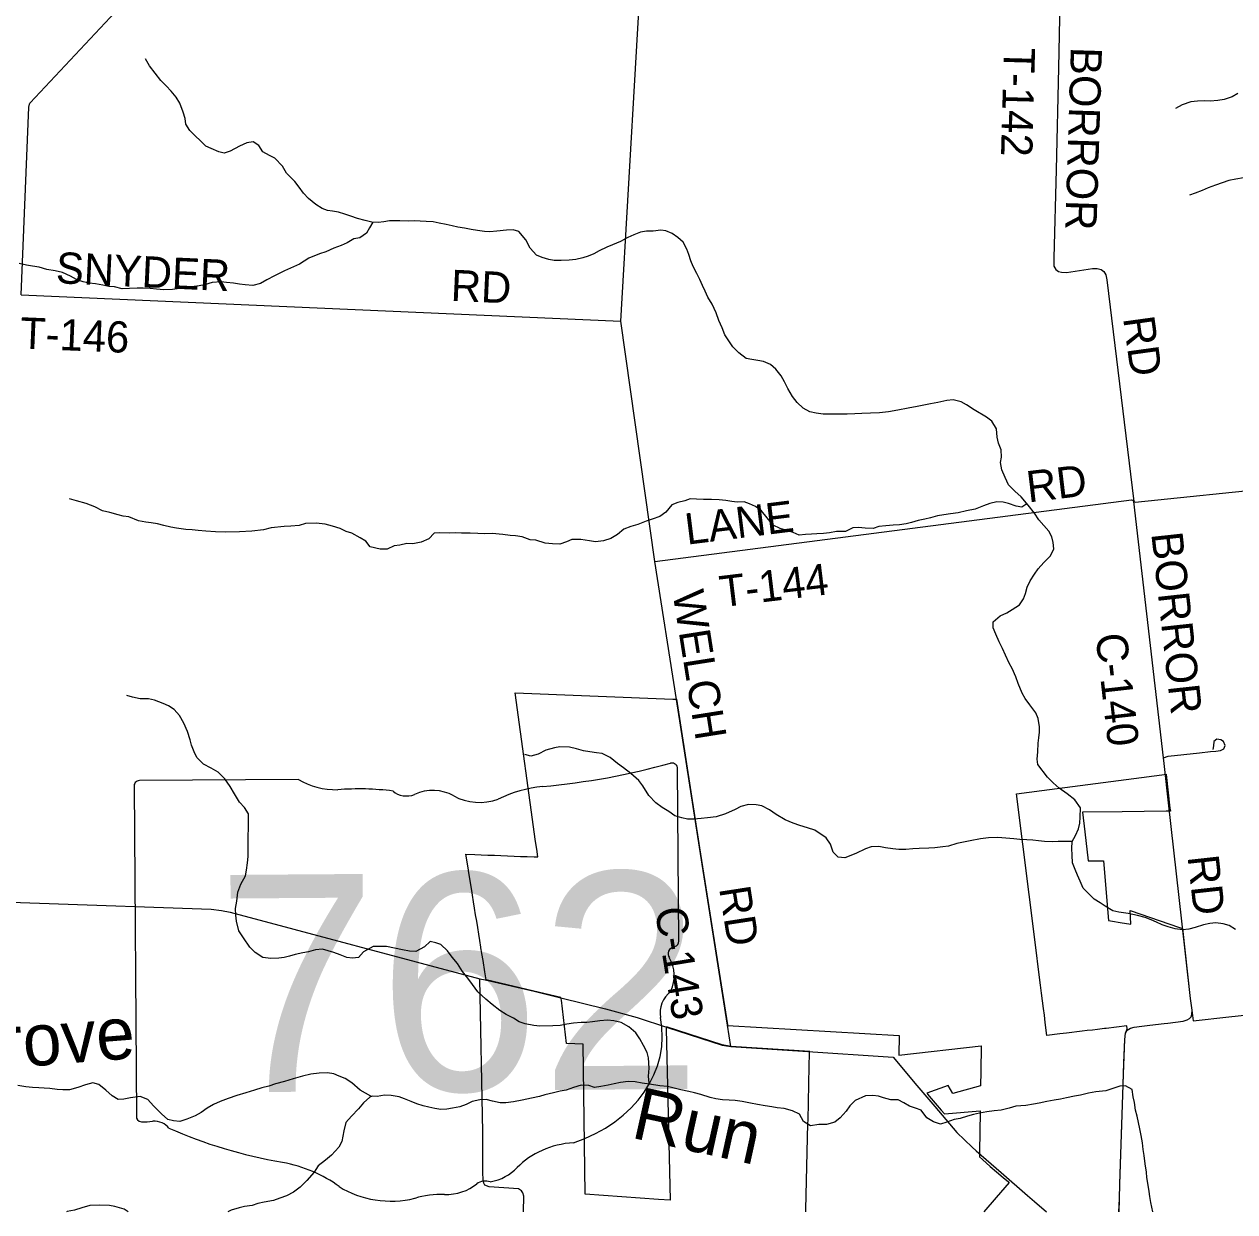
# Model space of a CAD drawing. Extents: x 114604 to 551442, y 316898 to 567001.
# Drawn here: x 179238 to 190868, y 317643 to 329055 of the extents above; entities that cross this region are included whole.
import ezdxf

# ---------------------------------------------------------------- set-up
doc = ezdxf.new("R2010")
doc.units = 0
for name, color, linetype in [('_CIVIL_CONSTRUCTION', 7, 'Continuous'), ('BD_X_Building', 7, 'Continuous'), ('GE_P_Alignment_1000_Cardinal_Points', 7, 'Continuous'), ('GE_P_Alignment_100_Stations', 7, 'Continuous'), ('GE_P_Alignment_500_Bearings', 7, 'Continuous'), ('GE_P_Alignment_500_Curve_Data', 7, 'Continuous'), ('PM_P_Cells', 7, 'Continuous'), ('PM_P_CL_Double_Solid', 7, 'Continuous'), ('PM_P_Crosswalk', 7, 'Continuous'), ('PM_P_Stop_Line', 7, 'Continuous')]:
    doc.layers.add(name, color=color, linetype=linetype)

msp = doc.modelspace()

# ---------------------------------------------------------------- linework, layer by layer
at = {"layer": '_CIVIL_CONSTRUCTION'}
for p, q in [((187814, 318858), (187986, 318656)), ((188944, 317742), (189058, 317643))]:
    msp.add_line(p, q, dxfattribs=at)
for points in [[(171255, 325243), (172108, 323234), (172499, 322309), (172537, 322236), (172596, 322172), (172685, 322099), (173053, 321844), (173629, 321425), (174426, 320802), (174474, 320772), (174528, 320749), (174593, 320740), (177732, 320667), (181033, 320552), (181132, 320540), (181218, 320522), (183615, 319883), (183667, 319871)], [(183667, 319871), (184136, 319762), (184394, 319699)], [(184394, 319699), (184822, 319594), (185128, 319509), (185417, 319415)], [(185417, 319415), (185736, 319312), (185943, 319245), (186028, 319231), (186719, 319186)], [(186719, 319186), (187585, 319130), (187814, 318858)], [(187986, 318656), (188198, 318405), (188345, 318265)], [(188345, 318265), (188383, 318228), (188624, 318020)], [(188624, 318020), (188876, 317801), (188944, 317742)]]:
    msp.add_lwpolyline(points, dxfattribs=at)
at = {"layer": 'GE_P_Alignment_1000_Cardinal_Points'}
msp.add_line((179210, 326456), (184971, 326203), dxfattribs=at)
for points in [[(179296, 328300), (180881, 329993), (181072, 330250)], [(189199, 329914), (189174, 328636), (189152, 327657), (189128, 326810), (189130, 326730), (189147, 326697), (189173, 326678), (189202, 326672), (189252, 326669), (189502, 326707), (189546, 326708), (189585, 326699), (189610, 326679), (189628, 326647), (189639, 326599), (189897, 324469)], [(179210, 326456), (179282, 328258), (179290, 328287), (179292, 328296), (179296, 328300)], [(185296, 323893), (189875, 324485), (189884, 324480), (189897, 324469)], [(190182, 322006), (190229, 322021), (190529, 322053), (190634, 322067), (190687, 322071), (190729, 322077), (190762, 322093), (190776, 322123), (190760, 322163), (190735, 322179), (190696, 322184), (190668, 322161), (190662, 322122), (190658, 322087)], [(184036, 317643), (184039, 317793), (184029, 317827), (184014, 317845), (183987, 317863), (183706, 317884), (183663, 317900), (183655, 317918), (183647, 317950), (183643, 318022), (183643, 318408), (183615, 319883)]]:
    msp.add_lwpolyline(points, dxfattribs=at)
at = {"layer": 'GE_P_Alignment_100_Stations'}
for points in [[(186748, 317643), (186748, 317665), (186767, 318491), (186768, 318525), (186780, 319042), (186783, 319164), (186784, 319184), (186027, 319233), (185942, 319248), (185407, 319422), (185406, 319400), (185443, 317756), (185333, 317763), (184628, 317812), (184609, 319255), (184448, 319262), (184399, 319677), (184394, 319701), (184135, 319765), (183675, 319872), (183672, 319893), (183670, 319911), (183664, 319948), (183646, 320058), (183635, 320125), (183629, 320165), (183626, 320181), (183625, 320187), (183615, 320249), (183605, 320311), (183595, 320374), (183585, 320436), (183575, 320498), (183565, 320560), (183555, 320623), (183545, 320685), (183538, 320731), (183535, 320747), (183525, 320809), (183511, 320900), (183503, 320950), (183482, 321079), (183566, 321076), (183629, 321074), (183692, 321071), (183755, 321069), (183818, 321066), (183881, 321064), (183944, 321061), (184007, 321059), (184070, 321057), (184136, 321054), (184172, 321053), (184162, 321128), (184151, 321203), (183956, 322629), (185468, 322569), (185503, 322569), (185727, 321142), (185994, 319441), (185995, 319433), (187645, 319339), (187641, 319148), (188432, 319239), (188428, 318991), (188425, 318855), (188158, 318780), (188114, 318858), (187910, 318782), (187932, 318756), (188048, 318621), (188078, 318585), (188421, 318613), (188421, 318600), (188416, 318224), (188415, 318170), (188443, 318145), (188517, 318080), (188579, 318026), (188644, 317972), (188693, 317930), (188700, 317924), (188576, 317780), (188458, 317643)], [(189755, 317643), (189759, 317772), (189764, 317911), (189792, 318768), (189802, 319075), (189811, 319299), (189818, 319361), (189831, 319391), (189833, 319403), (189830, 319429), (189633, 319405), (189617, 319404), (189549, 319396), (189500, 319390), (189450, 319384), (189400, 319378), (189351, 319372), (189301, 319367), (189251, 319361), (189186, 319353), (189063, 319339), (189047, 319463), (189039, 319532), (189030, 319597), (189021, 319671), (189012, 319745), (189002, 319820), (188990, 319919), (188953, 320209), (188770, 321661), (189015, 321692), (189898, 321807), (190168, 321842), (190208, 321847), (190212, 321815), (190245, 321523), (190249, 321492), (190209, 321492), (189785, 321487), (189404, 321483), (189426, 321293), (189459, 321015), (189607, 321016), (189653, 320441), (189692, 320435), (189767, 320424), (189868, 320408), (189864, 320540), (190336, 320376), (190365, 320365), (190440, 319694), (190455, 319582), (190468, 319479), (190809, 319516), (192176, 319665)]]:
    msp.add_lwpolyline(points, dxfattribs=at)
at = {"layer": 'GE_P_Alignment_500_Bearings'}
for p, q in [((185727, 321148), (185504, 322567)), ((190231, 321573), (190188, 321952)), ((190358, 320436), (190231, 321573)), ((185995, 319438), (185727, 321148)), ((186028, 319231), (185995, 319438))]:
    msp.add_line(p, q, dxfattribs=at)
for points in [[(185504, 322567), (185296, 323893), (184971, 326203), (185191, 330009)], [(189897, 324469), (189911, 324463), (192647, 324743)], [(190188, 321952), (190182, 322006), (189897, 324469)], [(190448, 319517), (190454, 319538), (190457, 319580), (190442, 319694), (190358, 320436)], [(190189, 319453), (190226, 319457), (190371, 319475), (190409, 319489), (190433, 319502), (190448, 319517)], [(189765, 317908), (189793, 318766), (189800, 318967), (189812, 319299), (189819, 319359), (189833, 319388), (189867, 319409)], [(189867, 319409), (189900, 319417), (189975, 319428)], [(189975, 319428), (190051, 319438), (190189, 319453)], [(189757, 317643), (189760, 317769), (189765, 317908)]]:
    msp.add_lwpolyline(points, dxfattribs=at)
at = {"layer": 'GE_P_Alignment_500_Curve_Data'}
for p, q in [((181874, 321798), (180345, 321787)), ((185526, 320245), (185514, 321903)), ((180294, 321732), (180317, 318562)), ((185525, 320245), (185526, 320245))]:
    msp.add_line(p, q, dxfattribs=at)
for centre, major_axis, ratio, start_param, end_param in [((183623, 326133), (5537, 40), 0.800001, 4.814395, 5.042369), ((185456, 321909), (58.1, 0.4), 0.8, 6.141152, 7.989035), ((182235, 322169), (587, 4), 0.8, 4.042523, 4.731795), ((180354, 321739), (60.5, 0.4), 0.8, 1.712693, 3.28349), ((182445, 320022), (2106, 15), 0.8, 1.404758, 1.657858), ((182911, 321774), (169, 1), 0.8, 3.836095, 5.185415), ((183162, 321410), (352, 3), 0.8, 0.950623, 2.079405), ((184368, 320848), (1114, 8), 0.8, 1.699011, 2.107814), ((183612, 321915), (423, 3), 0.8, 4.081561, 5.145723), ((185513, 320123), (89.9, 0.6), 0.8, 1.883978, 3.671073), ((185464, 320238), (62.2, 0.4), 0.8, 5.05454, 6.418171), ((184942, 319909), (540, 4), 0.8, 5.934695, 6.695948), ((185739, 319552), (393, 3), 0.8, 2.387724, 3.262537), ((183983, 319328), (1385, 10), 0.8, 5.101753, 6.440018), ((180377, 318556), (61, 0.4), 0.8, 3.00124, 4.508301), ((180384, 318880), (466, 3), 0.8, 4.665946, 4.897461), ((180483, 318380), (168, 1), 0.8, 0.519207, 1.627899), ((182582, 321244), (3998, 29), 0.8, 4.195996, 4.48896), ((184578, 317703), (758, 5), 0.8, 1.647645, 2.488434), ((181420, 317146), (1251, 9), 0.8, 0.823519, 1.323588), ((183613, 318279), (447, 3), 0.8, 4.937069, 5.64225), ((182764, 318381), (794, 6), 0.8, 4.026481, 4.996735), ((183282, 318147), (423, 3), 0.8, 4.691044, 5.507374), ((183667, 317843), (119, 1), 0.8, 1.147584, 2.315152), ((183230, 317288), (652, 5), 0.8, 1.495662, 1.94098)]:
    msp.add_ellipse(centre, major_axis=major_axis, ratio=ratio, start_param=start_param, end_param=end_param, dxfattribs=at)
at = {"layer": 'PM_P_Cells'}
for points in [[(185603, 326893), (185568, 326959), (185518, 327006), (185463, 327043), (185403, 327070), (185353, 327077), (185279, 327066), (185215, 327065), (185159, 327056), (185095, 327031), (185038, 327004), (184965, 326967), (184891, 326935), (184835, 326914), (184762, 326877), (184709, 326848), (184657, 326827), (184605, 326810), (184538, 326795), (184474, 326788), (184396, 326785), (184328, 326783), (184278, 326795), (184215, 326814), (184161, 326835), (184098, 326902), (184057, 326983), (183989, 327063), (183935, 327080), (183871, 327077), (183779, 327065), (183712, 327060), (183660, 327063), (183593, 327074), (183533, 327083), (183467, 327094), (183405, 327105), (183349, 327116), (183293, 327131), (183226, 327144), (183166, 327155), (183100, 327160), (183042, 327163), (182990, 327164), (182926, 327163), (182848, 327164), (182748, 327164), (182692, 327157), (182639, 327148), (182579, 327153), (182512, 327168), (182440, 327189), (182376, 327210), (182319, 327231), (182257, 327248), (182201, 327257), (182151, 327264), (182099, 327285), (182040, 327323), (181969, 327380), (181922, 327433), (181881, 327488), (181837, 327542), (181759, 327625), (181718, 327690), (181647, 327767), (181593, 327792), (181530, 327829), (181491, 327891), (181438, 327926), (181377, 327915), (181307, 327882), (181218, 327836), (181158, 327817), (181108, 327828), (181034, 327861), (180983, 327884), (180933, 327934), (180880, 327983), (180829, 328032), (180792, 328094), (180783, 328150), (180764, 328210), (180733, 328295), (180698, 328353), (180649, 328412), (180602, 328464), (180551, 328513), (180441, 328655), (180404, 328723)], [(190898, 328390), (190843, 328357), (190765, 328330), (190704, 328323), (190632, 328317), (190576, 328318), (190510, 328315), (190446, 328310), (190362, 328279), (190297, 328246)], [(191590, 327427), (191540, 327436), (191487, 327467), (191422, 327530), (191348, 327549), (191292, 327572), (191227, 327585), (191133, 327588), (191069, 327585), (191008, 327581), (190952, 327579), (190878, 327567), (190812, 327552), (190745, 327531), (190683, 327508), (190611, 327483), (190554, 327458), (190488, 327432), (190433, 327411)], [(182586, 327153), (182556, 327097), (182526, 327046), (182463, 327003), (182405, 326992), (182340, 326953), (182282, 326928), (182211, 326902), (182135, 326867), (182074, 326848), (181973, 326806), (181882, 326748), (181824, 326725), (181739, 326686), (181643, 326638), (181570, 326599), (181507, 326565), (181435, 326544), (181361, 326551), (181305, 326558), (181249, 326567), (181181, 326574), (181129, 326579), (181045, 326574), (180971, 326552), (180919, 326542), (180848, 326532), (180788, 326521), (180730, 326514), (180662, 326507), (180580, 326504), (180508, 326509), (180448, 326516), (180380, 326520), (180324, 326517), (180248, 326514), (180178, 326513), (180106, 326530), (180052, 326535), (179994, 326546), (179922, 326559), (179863, 326568), (179803, 326581), (179739, 326602), (179684, 326635), (179606, 326668), (179534, 326685), (179455, 326699), (179383, 326720), (179319, 326729), (179261, 326738), (179189, 326755)], [(188992, 322253), (188993, 322303), (188980, 322385), (188955, 322439), (188900, 322514), (188855, 322576), (188824, 322627), (188788, 322721), (188765, 322785), (188728, 322864), (188701, 322916), (188664, 322992), (188635, 323057), (188604, 323119), (188571, 323193), (188548, 323256), (188547, 323313), (188614, 323370), (188677, 323399), (188729, 323430), (188800, 323477), (188837, 323532), (188856, 323585), (188873, 323645), (188902, 323706), (188943, 323770), (188980, 323823), (189033, 323882), (189096, 323947), (189129, 324014), (189122, 324074), (189109, 324128), (189080, 324184), (189033, 324239), (188986, 324291), (188943, 324358), (188882, 324433), (188815, 324512), (188754, 324569), (188695, 324629), (188662, 324700), (188631, 324772), (188618, 324842), (188627, 324894), (188622, 324964), (188599, 325028), (188584, 325086), (188580, 325168), (188535, 325242), (188483, 325279), (188365, 325349), (188289, 325398), (188238, 325425), (188162, 325446), (188102, 325439), (188016, 325421), (187943, 325406), (187879, 325393), (187817, 325380), (187731, 325367), (187632, 325347), (187540, 325329), (187454, 325322), (187368, 325318), (187286, 325315), (187217, 325312), (187143, 325309), (187065, 325309), (186993, 325308), (186915, 325309), (186845, 325318), (186786, 325331), (186720, 325364), (186663, 325419), (186618, 325476), (186575, 325554), (186542, 325619), (186509, 325675), (186458, 325740), (186407, 325784), (186341, 325813), (186287, 325822), (186227, 325833), (186174, 325844), (186104, 325897), (186047, 325956), (186006, 326011), (185969, 326071), (185942, 326137), (185912, 326208), (185885, 326282), (185846, 326364), (185807, 326433), (185780, 326491), (185753, 326545), (185728, 326602), (185699, 326658), (185666, 326728), (185641, 326781), (185622, 326841), (185603, 326893)], [(182331, 324179), (182273, 324208), (182201, 324231), (182128, 324250), (182042, 324262), (181940, 324258), (181879, 324237), (181801, 324232), (181735, 324229), (181609, 324217), (181536, 324197), (181424, 324182), (181306, 324178), (181174, 324175), (181076, 324176), (180982, 324184), (180910, 324189), (180852, 324196), (180792, 324201), (180702, 324212), (180646, 324221), (180581, 324238), (180519, 324253), (180459, 324264), (180407, 324269), (180335, 324284), (180242, 324320), (180190, 324329), (180140, 324340), (180060, 324363), (179989, 324378), (179917, 324417), (179834, 324448), (179740, 324474), (179672, 324493)], [(188871, 324446), (188823, 324414), (188768, 324425), (188694, 324448), (188642, 324461), (188582, 324464), (188514, 324449), (188454, 324428), (188375, 324395), (188289, 324379), (188210, 324360), (188138, 324349), (188072, 324341), (188012, 324330), (187943, 324311), (187891, 324300), (187827, 324285), (187763, 324268), (187710, 324255), (187646, 324246), (187586, 324241), (187516, 324236), (187448, 324229), (187393, 324210), (187317, 324212), (187252, 324219), (187197, 324216), (187129, 324181), (187041, 324180), (186975, 324169), (186918, 324162), (186852, 324159), (186800, 324156), (186744, 324151), (186684, 324144), (186624, 324171), (186555, 324194), (186501, 324209), (186433, 324240), (186375, 324313), (186322, 324378), (186264, 324419), (186207, 324445), (186153, 324464), (186087, 324463), (186035, 324470), (185979, 324477), (185915, 324484), (185841, 324488), (185763, 324489), (185695, 324492), (185637, 324495), (185583, 324474), (185517, 324459), (185460, 324438), (185401, 324365), (185344, 324326), (185272, 324300), (185214, 324281), (185133, 324248), (185067, 324229), (184998, 324202), (184937, 324150), (184873, 324113), (184804, 324090), (184726, 324081), (184670, 324090), (184586, 324102), (184500, 324103), (184448, 324082), (184384, 324059), (184314, 324062), (184242, 324069), (184152, 324097), (184100, 324100), (184023, 324129), (183957, 324138), (183907, 324141), (183835, 324150), (183735, 324160), (183661, 324159), (183597, 324162), (183521, 324165), (183439, 324163), (183385, 324166), (183319, 324165), (183231, 324166), (183175, 324165), (183126, 324110), (183053, 324079), (182973, 324063), (182913, 324066), (182847, 324049), (182793, 324042), (182726, 324011), (182658, 324010), (182562, 324032), (182519, 324086), (182466, 324121), (182384, 324164), (182331, 324179)], [(180624, 322506), (180573, 322527), (180491, 322560), (180431, 322573), (180353, 322571), (180280, 322590), (180224, 322605)], [(185251, 318869), (185241, 318878), (185236, 318946), (185241, 319022), (185235, 319124), (185222, 319174), (185189, 319242), (185152, 319305), (185115, 319363), (185046, 319422), (184972, 319461), (184903, 319479), (184841, 319484), (184767, 319477), (184698, 319470), (184644, 319463), (184588, 319462), (184516, 319455), (184452, 319446), (184386, 319433), (184318, 319430), (184193, 319427), (184135, 319432), (184050, 319451), (183992, 319470), (183939, 319505), (183867, 319538), (183806, 319579), (183735, 319634), (183673, 319685), (183595, 319756), (183546, 319826), (183499, 319889), (183450, 319952), (183399, 320028), (183350, 320089), (183305, 320150), (183242, 320212), (183192, 320229), (183138, 320242), (183083, 320189), (183001, 320145), (182939, 320148), (182873, 320159), (182795, 320178), (182717, 320193), (182647, 320193), (182591, 320193), (182496, 320141), (182449, 320088), (182393, 320081), (182339, 320088), (182272, 320111), (182212, 320134), (182105, 320168), (182036, 320161), (181970, 320142), (181914, 320131), (181840, 320116), (181787, 320099), (181735, 320086), (181683, 320079), (181607, 320076), (181529, 320088), (181458, 320135), (181407, 320187), (181344, 320276), (181301, 320343), (181277, 320435), (181270, 320493), (181269, 320557), (181282, 320628), (181289, 320716), (181320, 320793), (181364, 320872), (181373, 320926), (181384, 320998), (181389, 321057), (181390, 321113), (181391, 321185), (181390, 321253), (181393, 321329), (181393, 321406), (181394, 321466), (181355, 321527), (181305, 321581), (181257, 321658), (181216, 321730), (181167, 321803), (181102, 321868), (181033, 321905), (180961, 321944), (180896, 322009), (180871, 322063), (180846, 322128), (180833, 322180), (180806, 322258), (180772, 322340), (180731, 322411), (180680, 322471), (180624, 322506)], [(190876, 320356), (190814, 320395), (190757, 320410), (190685, 320419), (190627, 320414), (190568, 320401), (190486, 320375), (190426, 320358), (190366, 320353), (190294, 320362), (190228, 320381), (190170, 320402), (190115, 320425), (190063, 320448), (190007, 320471), (189932, 320492), (189842, 320511), (189754, 320523), (189696, 320534), (189623, 320579), (189573, 320613), (189516, 320648), (189465, 320699), (189412, 320754), (189383, 320822), (189358, 320878), (189335, 320933), (189308, 320997), (189305, 321071), (189302, 321133), (189307, 321202), (189338, 321260), (189367, 321323), (189380, 321379), (189383, 321436), (189384, 321526), (189332, 321603), (189258, 321660), (189181, 321715), (189124, 321764), (189069, 321819), (188975, 321942), (188970, 321992), (188975, 322062), (188980, 322145), (188985, 322199), (188992, 322253)], [(189307, 321201), (189171, 321201), (189113, 321198), (189041, 321201), (188981, 321208), (188929, 321213), (188871, 321218), (188803, 321221), (188745, 321228), (188669, 321235), (188591, 321240), (188501, 321236), (188425, 321227), (188325, 321207), (188260, 321194), (188196, 321181), (188118, 321158), (188064, 321149), (187987, 321141), (187929, 321136), (187837, 321133), (187775, 321132), (187707, 321125), (187641, 321124), (187583, 321131), (187513, 321142), (187449, 321152), (187373, 321151), (187321, 321132), (187226, 321087), (187123, 321045), (187059, 321052), (187008, 321099), (186985, 321175), (186942, 321238), (186832, 321311), (186762, 321333), (186690, 321356), (186625, 321379), (186547, 321410), (186462, 321461), (186397, 321506), (186323, 321543), (186271, 321554), (186197, 321557), (186121, 321539), (186069, 321510), (185976, 321467), (185885, 321439), (185803, 321428), (185743, 321423), (185671, 321417), (185611, 321416), (185555, 321428), (185487, 321448), (185430, 321490), (185366, 321529), (185305, 321572), (185238, 321645), (185182, 321736), (185143, 321788), (185066, 321856), (184995, 321911), (184939, 321951), (184866, 322009), (184791, 322046), (184735, 322053), (184671, 322062), (184611, 322073), (184543, 322092), (184478, 322107), (184384, 322110), (184331, 322101), (184249, 322079), (184176, 322040), (184104, 322021), (184046, 322036)], [(188100, 318506), (188040, 318487), (187974, 318508), (187909, 318545), (187856, 318619), (187802, 318640), (187742, 318657), (187689, 318690), (187633, 318719), (187563, 318720), (187494, 318737), (187444, 318756), (187392, 318761), (187320, 318758), (187221, 318712), (187170, 318663), (187133, 318610), (187078, 318547), (187026, 318504), (186945, 318481), (186873, 318482), (186793, 318468), (186726, 318511), (186687, 318583), (186619, 318614), (186538, 318635), (186470, 318643), (186420, 318651), (186356, 318662), (186282, 318674), (186216, 318687), (186136, 318702), (186067, 318713), (186011, 318716), (185947, 318719), (185883, 318730), (185829, 318741), (185737, 318770), (185678, 318785), (185624, 318798), (185546, 318814), (185482, 318831), (185418, 318846), (185345, 318855), (185245, 318870), (185175, 318880), (185107, 318893), (185039, 318896), (184965, 318887), (184907, 318874), (184848, 318859), (184776, 318848), (184716, 318839), (184662, 318856), (184588, 318859), (184514, 318837), (184445, 318812), (184387, 318801), (184323, 318786), (184241, 318768), (184188, 318752), (184112, 318734), (184022, 318717), (183939, 318701), (183865, 318690), (183811, 318689), (183737, 318708), (183676, 318723), (183614, 318720), (183543, 318703), (183483, 318674), (183422, 318652), (183354, 318639), (183298, 318630), (183240, 318625), (183184, 318636), (183126, 318649), (183070, 318663), (183011, 318680), (182957, 318703), (182893, 318728), (182840, 318747), (182764, 318762), (182700, 318763), (182630, 318751), (182568, 318754), (182464, 318811), (182384, 318882), (182322, 318925), (182263, 318948), (182211, 318969), (182151, 318978), (182071, 318975), (181993, 318965), (181912, 318946), (181822, 318920), (181740, 318897), (181651, 318873), (181589, 318852), (181520, 318833), (181450, 318812)], [(181450, 318812), (181366, 318788), (181281, 318761), (181199, 318731), (181120, 318702), (181058, 318673), (180997, 318640), (180938, 318597), (180880, 318566), (180799, 318534), (180733, 318511), (180671, 318518), (180619, 318531), (180556, 318584), (180481, 318661), (180426, 318724), (180353, 318751), (180258, 318738), (180194, 318725), (180142, 318722), (180084, 318757), (180021, 318812), (179956, 318867), (179898, 318884), (179826, 318863), (179754, 318839), (179673, 318816), (179609, 318815), (179555, 318820), (179483, 318829), (179431, 318832), (179377, 318835), (179317, 318838), (179253, 318843), (179176, 318858)], [(190081, 317643), (190062, 317733), (190053, 317789), (190046, 317839), (190033, 317917), (190024, 317973), (190019, 318025), (190006, 318105), (189998, 318183), (189989, 318241), (189980, 318305), (189967, 318377), (189954, 318441), (189943, 318503), (189930, 318563), (189915, 318619), (189904, 318695), (189893, 318749), (189882, 318817), (189817, 318854), (189763, 318851), (189706, 318830), (189628, 318807), (189534, 318795), (189461, 318784), (189387, 318765), (189329, 318754), (189250, 318738), (189194, 318727), (189132, 318716), (189062, 318703), (188990, 318688), (188935, 318679), (188859, 318665), (188765, 318658), (188699, 318639), (188622, 318621), (188556, 318612), (188486, 318605), (188414, 318592), (188357, 318579), (188301, 318562), (188229, 318541), (188171, 318530), (188100, 318506)], [(182580, 318754), (182559, 318746), (182499, 318691), (182450, 318632), (182382, 318563), (182329, 318500), (182308, 318421), (182299, 318371), (182290, 318319), (182261, 318266), (182190, 318187), (182131, 318141), (182062, 318084), (182025, 318023), (181952, 317944), (181889, 317879), (181826, 317832), (181758, 317798), (181693, 317773), (181633, 317752), (181544, 317735), (181484, 317722), (181428, 317705), (181354, 317693), (181303, 317680), (181225, 317659), (181193, 317643)], [(180238, 317643), (180197, 317668), (180109, 317694), (180057, 317704), (179957, 317708), (179869, 317704), (179791, 317683), (179722, 317660), (179652, 317645), (179644, 317643)]]:
    msp.add_lwpolyline(points, dxfattribs=at)

# ---------------------------------------------------------------- texts
at = {"layer": 'BD_X_Building'}
for s, p in [('s', (182859, 319956)), ('r', (182859, 319956)), ('762', (182506, 319880))]:
    msp.add_text(s, height=1, rotation=0.4128, dxfattribs=at).set_placement(p)
at = {"layer": 'GE_P_Alignment_500_Curve_Data'}
msp.add_text('762', height=2088.5, rotation=0.4128, dxfattribs=at).set_placement((181091, 318791))
at = {"layer": 'PM_P_CL_Double_Solid'}
for s, rotation, p in [('BORROR', 276.2732, (190065, 324161)), ('WELCH', 278.9817, (185466, 323592)), ('C-140', 276.4794, (189529, 323188)), ('RD', 276.3195, (190413, 321057)), ('RD', 278.8211, (185913, 320752)), ('C-143', 279.2431, (185296, 320550))]:
    msp.add_text(s, height=300, rotation=rotation, dxfattribs=at).set_placement(p)
at = {"layer": 'PM_P_Crosswalk'}
for s, rotation, p in [('T-142', 268.4477, (188650, 328834)), ('BORROR', 268.2423, (189293, 328839)), ('SNYDER', 357.3184, (179538, 326567)), ('RD', 357.4517, (183332, 326397)), ('T-146', 357.6068, (179194, 325940)), ('RD', 277.844, (189794, 326231)), ('RD', 6.8626, (188885, 324459)), ('LANE', 7.1229, (185605, 324053)), ('T-144', 6.9094, (185937, 323452))]:
    msp.add_text(s, height=300, rotation=rotation, dxfattribs=at).set_placement(p)
at = {"layer": 'PM_P_Stop_Line'}
for s, rotation, p in [('Grove', 4.5296, (178501, 318978)), ('Run', 347.5283, (185056, 318358))]:
    msp.add_text(s, height=500, rotation=rotation, dxfattribs=at).set_placement(p)

doc.saveas('drawing.dxf')
